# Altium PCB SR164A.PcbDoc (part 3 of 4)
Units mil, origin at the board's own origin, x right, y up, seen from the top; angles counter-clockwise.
Board outline 6100 x 4100 mil, 6 copper layers (Top Layer, Signal Layer 1, Signal Layer 2, Signal Layer 3, Signal Layer 4, Bottom Layer), stack 61.4 mil thick; 254 components, 116 nets, 656 pads, 2538 vias.
Unrouted connection lines stored in the file: 13.
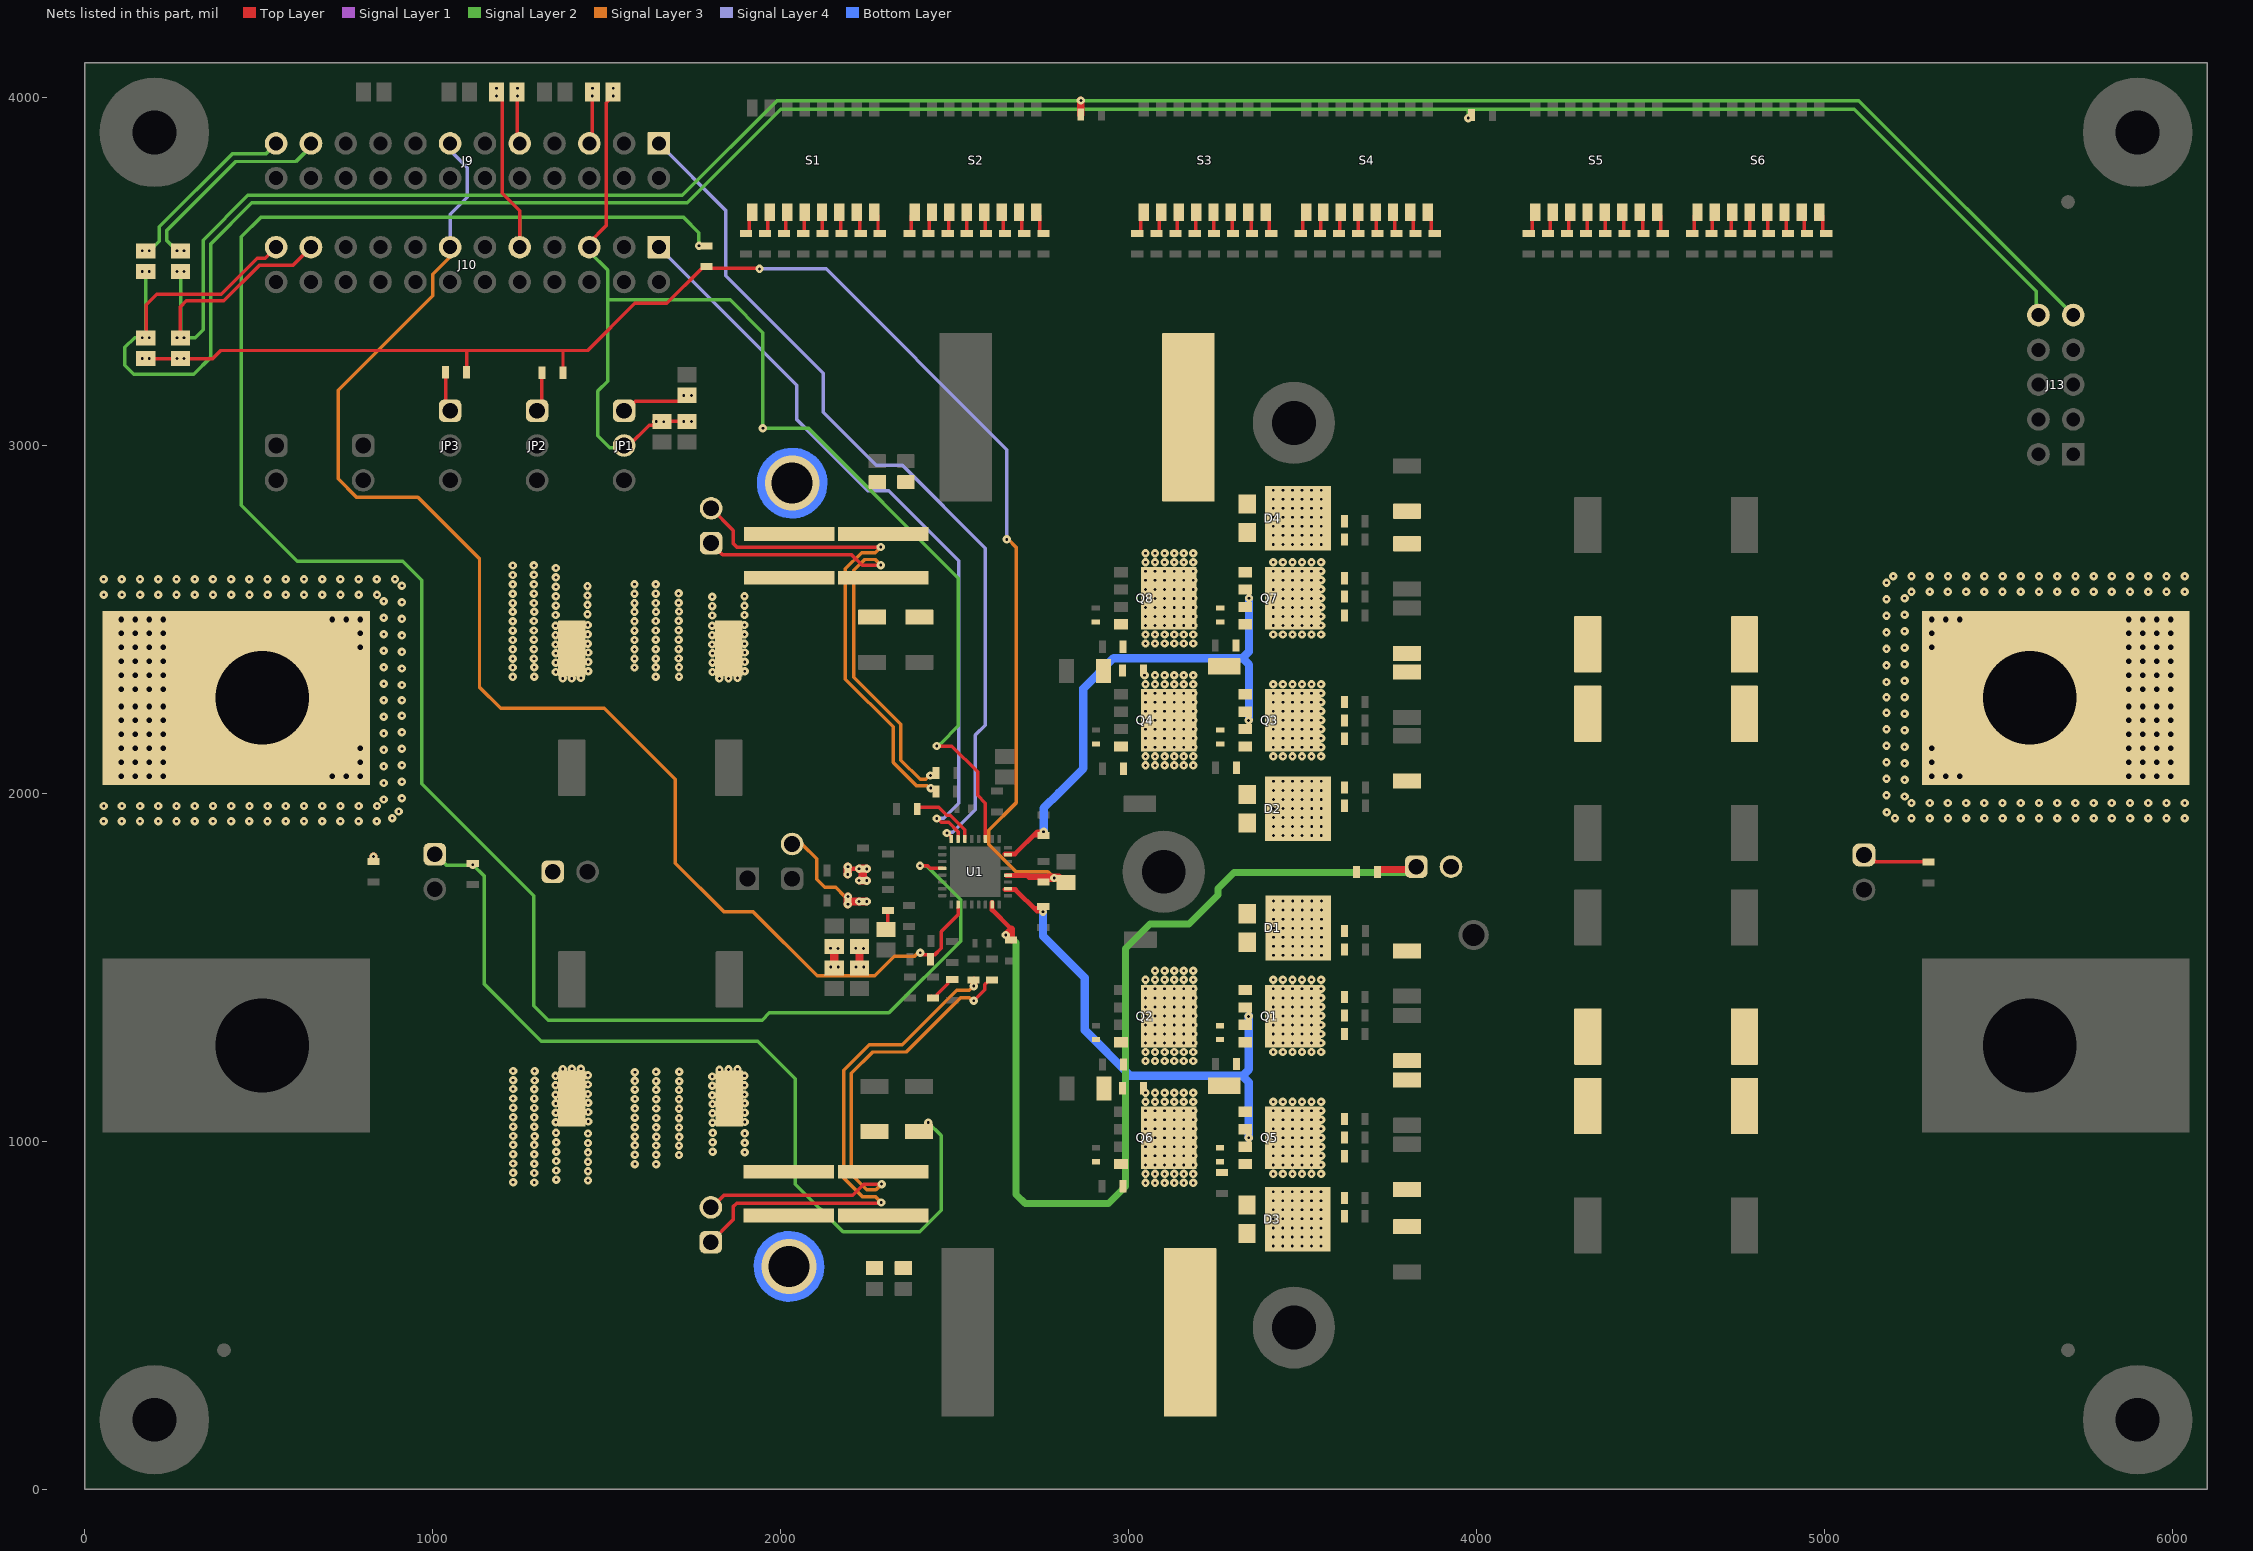
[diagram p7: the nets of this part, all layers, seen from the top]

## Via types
v1: diameter 24, hole 8, Top Layer to Bottom Layer, tented both sides, 2290 vias
v2: diameter 32, hole 16, Top Layer to Bottom Layer, 232 vias
v3: diameter 19.68, hole 7.87, Top Layer to Bottom Layer, tented both sides, 12 vias
v4: diameter 157.48, hole 118.11, Top Layer to Bottom Layer, tented both sides, 4 vias

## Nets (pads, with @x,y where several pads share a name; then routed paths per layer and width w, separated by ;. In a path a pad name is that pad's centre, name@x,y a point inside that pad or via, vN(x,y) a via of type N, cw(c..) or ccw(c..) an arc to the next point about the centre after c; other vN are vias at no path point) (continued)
NetC5_2: C5.2 R5.2 | length 87.8
  Top Layer w10: C5.2@2432.47,1417.54 C5.2@2437.93,1412.08 ; C5.2@2442.09,1414.7 2448.05,1414.7 2450.43,1417.08 2450.43,1423.04 2480.61,1453.22 2480.61,1460.72 2485.61,1465.72 R5.2@2493.11,1465.72
NetC9_2: C9.2 R29.2
NetC10_2: C10.2 R30.2
NetC16_1: C16.1 R8.1 | length 56.8
  Top Layer w10: C16.1@2302.35,1609.46 2308.21,1615.31 R8.1@2308.21,1663.87
NetC18_1: C18.1 JP5.2 R103.1 | length 364.2
  Top Layer w10: C18.1@2193.28,1692.52 2196.14,1689.66 v1(2225.5,1689.66) R103.1@2236.4,1689.66
  Top Layer w24: C18.1@2192.89,1689.7 R103.1@2247.29,1689.66 ; v1(2193.28,1681.63) C18.1@2193.28,1703.42
  Signal Layer 3 w10: JP5.2@2046.06,1854.79 2060.75,1854.79 2103.2,1812.34 2103.2,1753.81 2126.22,1730.79 2157.91,1730.79 2183.59,1705.11 v1@2193.45,1705.11
  other v1: 2247.46,1689.5 2193.45,1703.59
NetC19_1: C19.1 R103.2 R104.1 | length 178.5
  Top Layer w10: C19.1@2193.09,1778.19 C19.1@2199.65,1784.75 ; R104.1@2225.46,1779.28 2235.24,1779.28 2236.31,1780.34 2236.31,1749.75 R103.2@2236.4,1749.66
  Top Layer w12: C19.1@2197.32,1783.43 v1(2225.46,1783.43)
  Top Layer w24: v1(2193.09,1767.29) C19.1@2193.09,1789.08 ; v1(2225.46,1783.43) R104.1@2247.25,1783.43 ; v1(2225.5,1749.66) R103.2@2247.29,1749.66 ; R103.2@2236.31,1749.75 R104.1@2236.35,1783.43
  other v1: 2247.46,1749.5 2247.42,1783.26 2193.25,1789.25
NetJP1_1: JP1.1 R9.2 | length 202.3
  Top Layer w10: JP1.1@1550,3100 1555.52,3100 1583.34,3127.82 R9.2@1719.03,3127.82
  Top Layer w24: v1(1721.71,3143.92) R9.2@1743.51,3143.92
  other v1: 1743.67,3143.76
NetJP2_1: JP2.1 R89.1 | length 115
  Top Layer w10: JP2.1@1300,3100 1312.82,3112.82 1312.82,3207.44 R89.1@1314.41,3209.02
NetJP3_1: JP3.1 R90.1 | length 116.1
  Top Layer w10: R90.1@1037.3,3210.84 1038.03,3210.11 1038.03,3111.97 JP3.1@1050,3100
NetQ1_4: Q1.4 R21.1 R31.2
NetQ2_4: Q2.4 R22.2 R32.2
NetQ3_4: Q3.4 R23.2 R33.2
NetQ4_4: Q4.4 R24.1 R34.2
NetQ5_4: Q5.4 R25.1 R35.2
NetQ6_4: Q6.4 R26.2 R36.2
NetQ7_4: Q7.4 R27.2 R37.2
NetQ8_4: Q8.4 R28.1 R38.2
NetR41_1: R41.1 S1.1 | length 71.3
  Top Layer w10: R41.1@1900,3610 1905.09,3610 1910.09,3615 1910.09,3660.09 S1.1@1920,3670
NetR42_2: R42.2 S1.2 | length 67.7
  Top Layer w10: R42.2@1955,3610 1957.5,3610 1962.5,3615 1962.5,3662.5 S1.2@1970,3670
NetR43_1: R43.1 S1.3 | length 64.1
  Top Layer w10: R43.1@2010,3610 2015,3615 2015,3665 S1.3@2020,3670
NetR44_2: R44.2 S1.4 | length 62.1
  Top Layer w10: R44.2@2065,3610 2067.62,3612.62 2067.62,3667.62 S1.4@2070,3670
NetR45_1: R45.1 S1.5 | length 60
  Top Layer w10: R45.1@2120,3610 S1.5@2120,3670
NetR46_2: R46.2 S1.6 | length 62.1
  Top Layer w10: S1.6@2170,3670 2172.51,3667.49 2172.51,3612.49 R46.2@2175,3610
NetR47_2: R47.2 S1.7 | length 64.1
  Top Layer w10: S1.7@2220,3670 2227.52,3662.48 2227.52,3615 2230,3612.52 R47.2@2230,3610
NetR48_2: R48.2 S1.8 | length 66.3
  Top Layer w10: S1.8@2270,3670 2279.77,3660.23 2279.77,3615 2284.77,3610 R48.2@2285,3610
NetR49_2: R49.2 S2.1 | length 66.3
  Top Layer w10: R49.2@2370,3610 2370.23,3610 2375.23,3615 2375.23,3660.23 S2.1@2385,3670
NetR50_2: R50.2 S2.2 | length 64.1
  Top Layer w10: R50.2@2425,3610 2425,3612.52 2427.48,3615 2427.48,3662.48 S2.2@2435,3670
NetR51_2: R51.2 S2.3 | length 62.1
  Top Layer w10: R51.2@2480,3610 2482.49,3612.49 2482.49,3667.49 S2.3@2485,3670
NetR52_1: R52.1 S2.4 | length 60
  Top Layer w10: R52.1@2535,3610 S2.4@2535,3670
NetR53_2: R53.2 S2.5 | length 62.1
  Top Layer w10: S2.5@2585,3670 2587.38,3667.62 2587.38,3612.62 R53.2@2590,3610
NetR54_2: R54.2 S2.6 | length 64.1
  Top Layer w10: S2.6@2635,3670 2640,3665 2640,3615 R54.2@2645,3610
NetR55_2: R55.2 S2.7 | length 67.7
  Top Layer w10: S2.7@2685,3670 2692.5,3662.5 2692.5,3615 2697.5,3610 R55.2@2700,3610
NetR56_1: R56.1 S2.8 | length 71.3
  Top Layer w10: S2.8@2735,3670 2744.91,3660.09 2744.91,3615 2749.91,3610 R56.1@2755,3610
NetR57_1: R57.1 S3.1 | length 71.3
  Top Layer w10: R57.1@3025,3610 3030.09,3610 3035.09,3615 3035.09,3660.09 S3.1@3045,3670
NetR58_2: R58.2 S3.2 | length 67.7
  Top Layer w10: R58.2@3080,3610 3082.5,3610 3087.5,3615 3087.5,3662.5 S3.2@3095,3670
NetR59_1: R59.1 S3.3 | length 64.1
  Top Layer w10: R59.1@3135,3610 3140,3615 3140,3665 S3.3@3145,3670
NetR60_2: R60.2 S3.4 | length 62.1
  Top Layer w10: R60.2@3190,3610 3192.62,3612.62 3192.62,3667.62 S3.4@3195,3670
NetR61_1: R61.1 S3.5 | length 60
  Top Layer w10: R61.1@3245,3610 S3.5@3245,3670
NetR62_2: R62.2 S3.6 | length 62.1
  Top Layer w10: S3.6@3295,3670 3297.51,3667.49 3297.51,3612.49 R62.2@3300,3610
NetR63_2: R63.2 S3.7 | length 64.1
  Top Layer w10: S3.7@3345,3670 3352.52,3662.48 3352.52,3615 3355,3612.52 R63.2@3355,3610
NetR64_2: R64.2 S3.8 | length 66.3
  Top Layer w10: S3.8@3395,3670 3404.77,3660.23 3404.77,3615 3409.77,3610 R64.2@3410,3610
NetR65_2: R65.2 S4.1 | length 66.3
  Top Layer w10: R65.2@3495,3610 3495.23,3610 3500.23,3615 3500.23,3660.23 S4.1@3510,3670
NetR66_2: R66.2 S4.2 | length 64.1
  Top Layer w10: R66.2@3550,3610 3550,3612.52 3552.48,3615 3552.48,3662.48 S4.2@3560,3670
NetR67_2: R67.2 S4.3 | length 62.1
  Top Layer w10: R67.2@3605,3610 3607.49,3612.49 3607.49,3667.49 S4.3@3610,3670
NetR68_1: R68.1 S4.4 | length 60
  Top Layer w10: R68.1@3660,3610 S4.4@3660,3670
NetR69_2: R69.2 S4.5 | length 62.1
  Top Layer w10: S4.5@3710,3670 3712.38,3667.62 3712.38,3612.62 R69.2@3715,3610
NetR70_2: R70.2 S4.6 | length 64.1
  Top Layer w10: S4.6@3760,3670 3765,3665 3765,3615 R70.2@3770,3610
NetR71_2: R71.2 S4.7 | length 67.7
  Top Layer w10: S4.7@3810,3670 3817.5,3662.5 3817.5,3615 3822.5,3610 R71.2@3825,3610
NetR72_1: R72.1 S4.8 | length 71.3
  Top Layer w10: S4.8@3860,3670 3869.91,3660.09 3869.91,3615 3874.91,3610 R72.1@3880,3610
NetR73_1: R73.1 S5.1 | length 71.3
  Top Layer w10: R73.1@4150,3610 4155.09,3610 4160.09,3615 4160.09,3660.09 S5.1@4170,3670
NetR74_2: R74.2 S5.2 | length 67.7
  Top Layer w10: R74.2@4205,3610 4207.5,3610 4212.5,3615 4212.5,3662.5 S5.2@4220,3670
NetR75_1: R75.1 S5.3 | length 64.1
  Top Layer w10: R75.1@4260,3610 4265,3615 4265,3665 S5.3@4270,3670
NetR76_2: R76.2 S5.4 | length 62.1
  Top Layer w10: R76.2@4315,3610 4317.62,3612.62 4317.62,3667.62 S5.4@4320,3670
NetR77_1: R77.1 S5.5 | length 60
  Top Layer w10: R77.1@4370,3610 S5.5@4370,3670
NetR78_2: R78.2 S5.6 | length 62.1
  Top Layer w10: S5.6@4420,3670 4422.51,3667.49 4422.51,3612.49 R78.2@4425,3610
NetR79_2: R79.2 S5.7 | length 64.1
  Top Layer w10: S5.7@4470,3670 4477.52,3662.48 4477.52,3615 4480,3612.52 R79.2@4480,3610
NetR80_2: R80.2 S5.8 | length 66.3
  Top Layer w10: S5.8@4520,3670 4529.77,3660.23 4529.77,3615 4534.77,3610 R80.2@4535,3610
NetR81_2: R81.2 S6.1 | length 66.3
  Top Layer w10: R81.2@4620,3610.79 4620.23,3610.79 4625.23,3615.79 4625.23,3661.02 S6.1@4635,3670.79
NetR82_2: R82.2 S6.2 | length 64.1
  Top Layer w10: R82.2@4675,3610.79 4675,3613.31 4677.48,3615.79 4677.48,3663.27 S6.2@4685,3670.79
NetR83_2: R83.2 S6.3 | length 62.1
  Top Layer w10: R83.2@4730,3610.79 4732.49,3613.28 4732.49,3668.28 S6.3@4735,3670.79
NetR84_1: R84.1 S6.4 | length 60
  Top Layer w10: R84.1@4785,3610.79 S6.4@4785,3670.79
NetR85_2: R85.2 S6.5 | length 62.1
  Top Layer w10: S6.5@4835,3670.79 4837.38,3668.41 4837.38,3613.41 R85.2@4840,3610.79
NetR86_2: R86.2 S6.6 | length 64.1
  Top Layer w10: S6.6@4885,3670.79 4890,3665.79 4890,3615.79 R86.2@4895,3610.79
NetR87_2: R87.2 S6.7 | length 67.7
  Top Layer w10: S6.7@4935,3670.79 4942.5,3663.29 4942.5,3615.79 4947.5,3610.79 R87.2@4950,3610.79
NetR88_1: R88.1 S6.8 | length 71.3
  Top Layer w10: S6.8@4985,3670.79 4994.91,3660.88 4994.91,3615.79 4999.91,3610.79 R88.1@5005,3610.79
NetR91_2: R91.2 R93.1 | length 79.6
  Top Layer w24: v1(2215.85,1554.91) R93.1@2237.65,1554.91 ; v1(2216.62,1501.31) R91.2@2238.41,1501.31 ; R91.2@2226.78,1516.56 R93.1@2226.78,1552.6
  other v1: 2238.58,1501.15 2237.81,1554.74
NetR92_2: R92.2 R94.1 | length 79.6
  Top Layer w24: v1(2142.97,1554.91) R94.1@2164.76,1554.91 ; v1(2143.74,1501.31) R92.2@2165.53,1501.31 ; R92.2@2154.41,1515.86 R94.1@2154.41,1551.9
  other v1: 2165.7,1501.15 2164.93,1554.74
PGOOD: J10.9 R19.2 R98.1 U1.28 | length 6443.5
  Top Layer w10: v1(1183.28,4004.73) R98.1@1183.45,4004.9 ; R98.1@1183.54,4013.9 R98.1@1183.54,4015.75 ; R98.1@1187.99,4009.44 1199.69,3997.75 1199.69,3952.14 1199.69,3725.08 1250,3674.77 J10.9@1250,3570 ; v1(1765.12,3574.08) 1765.21,3574 1786.87,3574 R19.2@1786.95,3573.92 ; v1@2401.68,1792.54 2422.1,1792.54 2429.79,1784.84 U1.28@2464.51,1784.84
  Top Layer w24: R98.1@1183.45,4004.9 v1(1183.45,4026.69)
  Signal Layer 2 w10: J10.9@1250,3570 1250,3655.9 ; v1(1765.12,3574.08) 1765.12,3611.57 1720.79,3655.9 1308.61,3655.9 506.29,3655.9 449.9,3599.51 449.9,2828.38 610.96,2667.32 913.97,2667.32 968.87,2612.42 968.87,2027.91 1290.82,1705.96 1290.82,1389.65 1332.04,1348.43 1946.52,1348.43 1967.34,1369.25 2311.36,1369.25 2517.26,1575.15 2517.26,1592.6 2517.26,1694.42 2419.21,1792.47 v1(2400.54,1792.47)
  Signal Layer 3 w10: J10.9@1250,3555.3 J10.9@1250,3570
  Bottom Layer w24: v1@1183.45,4004.9 v1(1183.45,4026.69)
PGOOD_SEC: J9.9 R98.2 | length 182.8
  Top Layer w10: v1(1243.28,4004.73) 1243.28,3875.03 J9.9@1250,3868.31
  Top Layer w24: R98.2@1243.45,4004.9 v1(1243.45,4026.69)
  Bottom Layer w24: v1@1243.45,4004.9 v1(1243.45,4026.69)
RS1: J11.1 R1.1 R3.1 R11.2 R12.2 R16.2 | length 2089.8
  Top Layer w10: J11.1@1799.29,710.42 1863.12,774.25 1863.12,811.64 1873.22,821.74 v1@2286.79,821.74 ; R16.2@2554.63,1464.14 R16.2@2555.16,1463.61
  Top Layer w20: v1(2555.16,1446.33) R16.2@2555.16,1463.61
  Signal Layer 3 w10: v1(2288.9,824.49) 2273.1,840.29 2236.23,840.29 2181.63,894.89 2181.63,1204.43 2254.48,1277.28 2349.1,1277.28 2506.47,1434.65 2542.3,1434.65 2553.98,1446.33 v1(2555.16,1446.33)
  Bottom Layer w10: v4(2024,640.62) 2091.82,640.62 2104.57,627.87
  Bottom Layer w40: 2104.57,627.87 cw(c2024,640.62) 2104.84,629.72
RS2: J12.2 R2.2 R4.2 R13.1 R14.1 R18.2 | length 2101.6
  Top Layer w10: J12.2@1800,2819.54 1863.83,2755.71 1863.83,2718.32 1873.93,2708.22 v1@2287.5,2708.22 ; v1(2431.39,2015.34) 2440.92,2015.34 2445.92,2010.34 R18.2@2445.92,2005.78
  Signal Layer 3 w10: v1(2287.5,2708.14) 2271.36,2692 2232.68,2692 2186.11,2645.43 2186.11,2328.49 2323.33,2191.27 2323.33,2089.01 2389.56,2022.78 2420.16,2022.78 2426.91,2016.03 v1@2431.39,2016.03
  Bottom Layer w10: v4@1983,2892 v4(2033,2892) 2043.9,2881.1 2113.85,2881.1
  Bottom Layer w40: 2113.57,2879.25 cw(c2033,2892) 2113.85,2881.1
RT: R6.2 U1.22 | length 181.3
  Top Layer w10: R6.2@2400.95,1960.35 2454.57,1960.35 2477.41,1937.52 2487.35,1937.52 2529.47,1895.39 U1.22@2529.47,1869.49
SCL: J10.21 J13.9 R39.1 R102.1 R106.1 | length 7111.9
  Top Layer w10: v1(265,3310) v1(285,3310) ; R102.1@275,3310.86 275,3399.14 291.57,3415.71 399.65,3415.71 502.75,3518.81 598.81,3518.81 J10.21@650,3570
  Top Layer w22: R39.1@2862.44,3951.1 v1@2862.44,3991.42
  Signal Layer 1 w24: v1(265,3310) v1(285,3310) ; v1(265,3500) v1(285,3500)
  Signal Layer 2 w10: v1@275.52,3310 275.52,3499.48 276.05,3500 v1(285,3500) ; v1(285,3310) 317.5,3310 340.29,3332.79 340.29,3590.25 468.88,3718.84 1716.78,3718.84 1989.36,3991.42 v1(2862.94,3991.42) 5098.58,3991.42 J13.9@5715,3375
  Signal Layer 2 w24: v1(265,3310) 275.52,3310 v1(285,3310) ; v1(265,3500) 275.52,3500 v1(285,3500)
  Signal Layer 3 w24: v1(265,3310) v1(285,3310) ; v1(265,3500) v1(285,3500)
  Signal Layer 4 w24: v1(265,3310) v1(285,3310) ; v1(265,3500) v1(285,3500)
  Bottom Layer w24: v1(265,3310) v1(285,3310) ; v1(265,3500) v1(285,3500)
SCL_SEC: J9.21 R106.2 | length 693.2
  Signal Layer 1 w24: v1(265,3560) v1(285,3560)
  Signal Layer 2 w10: v1(265,3560) 235.89,3589.11 235.89,3618.13 434.06,3816.3 606.92,3816.3 650,3859.38 J9.21@650,3868.31
  Signal Layer 2 w24: v1(265,3560) v1(285,3560)
  Signal Layer 3 w24: v1(265,3560) v1(285,3560)
  Signal Layer 4 w24: v1(265,3560) v1(285,3560)
  Bottom Layer w24: v1(265,3560) v1(285,3560)
SDA: J10.23 J13.10 R40.1 R101.1 R105.1 | length 7401
  Top Layer w10: R101.1@176.53,3311.05 176.53,3405 206.57,3435.04 391.92,3435.04 495.36,3538.48 518.48,3538.48 J10.23@550,3570
  Top Layer w22: v1(3975.98,3941.04) R40.1@3983.2,3948.28
  Signal Layer 1 w24: v1(165,3310) v1(185,3310) ; v1(165,3500) v1(185,3500)
  Signal Layer 2 w10: v1(165,3310) 143.08,3310 115.03,3281.95 115.03,3230.35 140.86,3204.51 312.6,3204.51 362.61,3254.52 362.61,3580.35 479.62,3697.36 1731.13,3697.36 2000.47,3966.7 2852.48,3966.7 2852.63,3966.55 3975.98,3966.55 ; v1(165,3500) 175.4,3500 v1(185,3500) ; v1@174.92,3500 174.92,3310 v1(185,3310) ; v1(3975.98,3941.04) 3975.98,3966.55 ; J13.10@5609.09,3375.35 5609.09,3443.5 5086.04,3966.55 3975.98,3966.55
  Signal Layer 2 w24: v1(165,3310) 174.92,3310 v1(185,3310) ; v1(165,3500) 174.92,3500 v1(185,3500)
  Signal Layer 3 w24: v1(165,3310) v1(185,3310) ; v1(165,3500) v1(185,3500)
  Signal Layer 4 w24: v1(165,3310) v1(185,3310) ; v1(165,3500) v1(185,3500)
  Bottom Layer w24: v1(165,3310) v1(185,3310) ; v1(165,3500) v1(185,3500)
SDA_SEC: J9.23 R105.2 | length 614.7
  Signal Layer 1 w24: v1(165,3560) v1(185,3560)
  Signal Layer 2 w10: v1@186.76,3560.33 213.9,3587.47 213.9,3628.24 423.56,3837.9 519.59,3837.9 J9.23@550,3868.31
  Signal Layer 2 w24: v1(165,3560) v1(185,3560)
  Signal Layer 3 w24: v1(165,3560) v1(185,3560)
  Signal Layer 4 w24: v1(165,3560) v1(185,3560)
  Bottom Layer w24: v1(165,3560) v1(185,3560)
SS: C8.1 J9.13 J10.13 U1.2 | length 3997.4
  Top Layer w10: v1(2401.07,1542.1) 2404.86,1542.1 2411.12,1535.84 2426.16,1535.84 2431.16,1530.84 C8.1@2431.16,1523.34 ; C8.1@2436.16,1535.84 2442.17,1535.84 2461.41,1555.08 2461.41,1603.2 2509.79,1651.59 U1.2@2509.79,1673.7
  Signal Layer 3 w10: J10.13@1063.59,3555.76 999.85,3492.02 999.85,3430.33 728.49,3158.97 728.49,2904.1 780.85,2851.74 957.6,2851.74 1134.44,2674.9 1134.44,2305.16 1195,2244.6 1492.69,2244.6 1696.92,2040.37 1696.92,1799.95 1836.22,1660.64 1920.31,1660.64 2105.2,1475.74 2270.1,1475.74 2325.95,1531.6 2384.72,1531.6 v1@2402.44,1549.31
  Signal Layer 4 w10: J10.13@1050,3570 1050,3664.15 1099.5,3713.65 1099.5,3798.87 1060.52,3837.85 1060.52,3857.79 J9.13@1050,3868.31
SW1: C9.1 C13.1 D1.1 D1.2 D3.1 D3.2 L1.1 Q1.1 Q1.2 Q1.3 Q2.5 Q5.1 Q5.2 Q5.3 Q6.5 R31.1 R35.1 TP1.1 U1.10 | length 1428.8
  Top Layer w10: 2725.72,1672.26 C13.1@2755.72,1672.26
  Top Layer w13.5: U1.10@2644.7,1723.79 2674.71,1723.79 2736.9,1661.6 2752.72,1661.6 v1(2754.12,1660.21)
  Bottom Layer w24: v1(2754.12,1660.21) 2754.12,1589.91 2874.04,1469.99 2874.04,1319.43 3005.12,1188.35 3327.01,1188.35 ; v1(3345.56,1010.69) 3345.56,1169.79 3327.01,1188.35 ; v1@3345.56,1360.69 3345.56,1206.9 3327.01,1188.35
  other v1: 3048.51,880.71 3076.01,880.71 3103.51,880.71 3131.01,880.71 3158.51,880.71 3186.01,880.71 3048.51,906.63 3076.01,906.63 3103.51,906.63 3131.01,906.63 3158.51,906.63 3186.01,906.63 3048.51,932.56 3076.01,932.56 3103.51,932.56 3131.01,932.56 3158.51,932.56 3186.01,932.56 3048.51,958.49 3076.01,958.49 3103.51,958.49 3131.01,958.49 3158.51,958.49 3186.01,958.49 3048.51,984.41 3076.01,984.41 3103.51,984.41 3131.01,984.41 3158.51,984.41 3186.01,984.41 3048.51,1010.34 3076.01,1010.34 3103.51,1010.34 3131.01,1010.34 3158.51,1010.34 3186.01,1010.34 3048.51,1036.26 3076.01,1036.26 3103.51,1036.26 3131.01,1036.26 3158.51,1036.26 3186.01,1036.26 3048.51,1062.19 3076.01,1062.19 3103.51,1062.19 3131.01,1062.19 3158.51,1062.19 3186.01,1062.19 3048.51,1088.12 3076.01,1088.12 3103.51,1088.12 3131.01,1088.12 3158.51,1088.12 3186.01,1088.12 3048.51,1114.04 3076.01,1114.04 3103.51,1114.04 3131.01,1114.04 3158.51,1114.04 3186.01,1114.04 3048.51,1139.97 3076.01,1139.97 3103.51,1139.97 3131.01,1139.97 3158.51,1139.97 3186.01,1139.97 3048.55,1231.03 3076.05,1231.03 3103.55,1231.03 3131.05,1231.03 3158.55,1231.03 3186.05,1231.03 3048.55,1256.96 3076.05,1256.96 3103.55,1256.96 3131.05,1256.96 3158.55,1256.96 3186.05,1256.96 3048.55,1282.88 3076.05,1282.88 3103.55,1282.88 3131.05,1282.88 3158.55,1282.88 3186.05,1282.88 3048.55,1308.81 3076.05,1308.81 3103.55,1308.81 3131.05,1308.81 3158.55,1308.81 3186.05,1308.81 3048.55,1334.73 3076.05,1334.73 3103.55,1334.73 3131.05,1334.73 3158.55,1334.73 3186.05,1334.73 3345,1359.23 3048.55,1360.66 3076.05,1360.66 3103.55,1360.66 3131.05,1360.66 3158.55,1360.66 3186.05,1360.66 3048.55,1386.59 3076.05,1386.59 3103.55,1386.59 3131.05,1386.59 3158.55,1386.59 3186.05,1386.59 3048.55,1412.51 3076.05,1412.51 3103.55,1412.51 3131.05,1412.51 3158.55,1412.51 3186.05,1412.51 3048.55,1438.44 3076.05,1438.44 3103.55,1438.44 3131.05,1438.44 3158.55,1438.44 3186.05,1438.44 3048.55,1464.37 3076.05,1464.37 3103.55,1464.37 3131.05,1464.37 3158.55,1464.37 3186.05,1464.37 3076.05,1490.29 3103.55,1490.29 3131.05,1490.29 3158.55,1490.29 3186.05,1490.29
SW2: C10.1 C14.2 D2.1 D2.2 D4.1 D4.2 L2.2 Q3.1 Q3.2 Q3.3 Q4.5 Q7.1 Q7.2 Q7.3 Q8.5 R33.1 R37.1 TP2.1 U1.15 | length 1489
  Top Layer w10: 2728.05,1878.91 C14.2@2758.05,1878.91 ; v1(2755.75,1890.26) v1@2759.54,1890.26
  Top Layer w13.5: U1.15@2644.7,1826.21 2673.52,1826.21 2737.36,1890.04 2755.53,1890.04 v1(2755.75,1890.26)
  Bottom Layer w24: v1(2755.75,1890.26) 2755.75,1957.76 2799.59,2001.6 2870,2072.01 2870,2301.79 2957.06,2388.85 3327.3,2388.85 ; v1@3345.86,2211.2 3345.86,2370.3 3327.3,2388.85 ; v1(3345.86,2561.2) 3345.86,2407.41 3327.3,2388.85
  other v1: 3048.51,2080.7 3076.01,2080.7 3103.51,2080.7 3131.01,2080.7 3158.51,2080.7 3186.01,2080.7 3048.51,2106.63 3076.01,2106.63 3103.51,2106.63 3131.01,2106.63 3158.51,2106.63 3186.01,2106.63 3048.51,2132.56 3076.01,2132.56 3103.51,2132.56 3131.01,2132.56 3158.51,2132.56 3186.01,2132.56 3048.51,2158.48 3076.01,2158.48 3103.51,2158.48 3131.01,2158.48 3158.51,2158.48 3186.01,2158.48 3048.51,2184.41 3076.01,2184.41 3103.51,2184.41 3131.01,2184.41 3158.51,2184.41 3186.01,2184.41 3048.51,2210.34 3076.01,2210.34 3103.51,2210.34 3131.01,2210.34 3158.51,2210.34 3186.01,2210.34 3345,2210 3048.51,2236.26 3076.01,2236.26 3103.51,2236.26 3131.01,2236.26 3158.51,2236.26 3186.01,2236.26 3048.51,2262.19 3076.01,2262.19 3103.51,2262.19 3131.01,2262.19 3158.51,2262.19 3186.01,2262.19 3048.51,2288.11 3076.01,2288.11 3103.51,2288.11 3131.01,2288.11 3158.51,2288.11 3186.01,2288.11 3048.51,2314.04 3076.01,2314.04 3103.51,2314.04 3131.01,2314.04 3158.51,2314.04 3186.01,2314.04 3046.05,2339.96 3076.01,2339.97 3103.51,2339.97 3131.01,2339.97 3158.51,2339.97 3186.01,2339.97 3048.55,2431.03 3076.05,2431.03 3103.55,2431.03 3131.05,2431.03 3158.55,2431.03 3186.05,2431.03 3048.55,2456.96 3076.05,2456.96 3103.55,2456.96 3131.05,2456.96 3158.55,2456.96 3186.05,2456.96 3048.55,2482.88 3076.05,2482.88 3103.55,2482.88 3131.05,2482.88 3158.55,2482.88 3186.05,2482.88 3048.55,2508.81 3076.05,2508.81 3103.55,2508.81 3131.05,2508.81 3158.55,2508.81 3186.05,2508.81 3048.55,2534.73 3076.05,2534.73 3103.55,2534.73 3131.05,2534.73 3158.55,2534.73 3186.05,2534.73 3048.55,2560.66 3076.05,2560.66 3103.55,2560.66 3131.05,2560.66 3158.55,2560.66 3186.05,2560.66 3048.55,2586.59 3076.05,2586.59 3103.55,2586.59 3131.05,2586.59 3158.55,2586.59 3186.05,2586.59 3048.55,2612.51 3076.05,2612.51 3103.55,2612.51 3131.05,2612.51 3158.55,2612.51 3186.05,2612.51 3048.55,2638.44 3076.05,2638.44 3103.55,2638.44 3131.05,2638.44 3158.55,2638.44 3186.05,2638.44 3048.55,2664.37 3076.05,2664.37 3103.55,2664.37 3131.05,2664.37 3158.55,2664.37 3186.05,2664.37 3048.55,2690.29 3076.05,2690.29 3103.55,2690.29 3131.05,2690.29 3158.55,2690.29 3186.05,2690.29
SYNCIN: J9.1 U1.24 | length 2492.7
  Top Layer w10: v1(2477.8,1886.36) 2481.76,1882.4 2483.92,1882.4 2490.1,1876.22 U1.24@2490.1,1869.49
  Signal Layer 4 w10: J9.1@1650,3868.31 1842.71,3675.6 1842.71,3487.54 2122.17,3208.07 2122.17,3095.22 2274.36,2943.02 2350.09,2943.02 2588.29,2704.83 2588.29,2196.44 2559.74,2167.89 2559.74,2001.6 2559.74,1953.37 2494.36,1887.98 2479.42,1887.98 v1(2477.8,1886.36)
SYNCOUT: J10.1 U1.23 | length 2169.6
  Top Layer w10: v1(2448.55,1928.21) 2450.19,1928.21 2461.41,1917 2482.56,1917 2509.71,1889.85 2509.71,1869.57 U1.23@2509.79,1869.49
  Signal Layer 4 w10: J10.1@1650,3570 2046.34,3173.66 2046.34,3074.76 2250.92,2870.18 2311.14,2870.18 2512.26,2669.05 2512.26,2001.6 2512.26,1972.27 2468.21,1928.21 v1(2448.55,1928.21)
UVLO/EN: C20.1 J10.5 JP1.2 R10.1 R96.1 U1.19 | length 3760.6
  Top Layer w10: J10.5@1450,3570 1450,3583.11 1499.18,3632.29 1499.18,3985.27 v1(1518.64,4004.73) ; JP1.2@1550,3000 1563.11,3000 1621.83,3058.72 1635.97,3058.72 1642.48,3065.23 C20.1@1642.48,3068.72 ; C20.1@1646.53,3064.67 C20.1@1651.53,3069.67 ; C20.1@1653.53,3069.67 1664.22,3069.67 R10.1@1709.19,3069.67 ; R10.1@1715.19,3069.67 R10.1@1725.03,3069.67 ; v1(2448.5,2136.24) 2492.12,2136.24 2565.96,2062.4 2565.96,1994.38 2588.53,1971.81 U1.19@2588.53,1869.49
  Top Layer w24: R96.1@1518.81,4004.9 v1(1518.81,4026.69) ; v1(1642.26,3068.72) C20.1@1664.06,3068.72 ; v1(1721.71,3069.13) R10.1@1743.51,3069.13
  Signal Layer 2 w10: J10.5@1450,3556.89 1502.46,3504.43 1502.46,3418.6 ; JP1.2@1550,3000 1544.12,2994.12 1508.38,2994.12 1473.86,3028.64 1473.86,3156.68 1502.46,3185.28 1502.46,3418.6 ; v1(1948.82,3049.35) 1948.82,3324.59 1854.8,3418.6 1502.46,3418.6 ; v1@1948.82,3050.28 2079.72,3050.28 2510.91,2619.09 2510.91,2194.51 2459.65,2143.24 2459.29,2143.24 2451.77,2135.73 v1@2451.77,2135.37
  Bottom Layer w24: v1@1518.81,4004.9 v1(1518.81,4026.69)
  other v1: 1664.22,3068.55 1743.67,3068.96
UVLO/EN_SEC: J9.5 R96.2 | length 183.6
  Top Layer w10: J9.5@1450,3868.31 1458.64,3876.95 v1(1458.64,4004.73)
  Top Layer w24: R96.2@1458.81,4004.9 v1(1458.81,4026.69)
  Bottom Layer w24: v1@1458.81,4004.9 v1(1458.81,4026.69)
VCC: C3.1 C4.1 R19.1 R89.2 R90.2 R101.2 R102.2 U1.12 | length 4784.9
  Top Layer w10: R101.2@167.58,3250.98 R101.2@185,3250.98 ; v1(185,3250) v1(265,3250) ; R102.2@265,3250.98 R102.2@285,3250.98 ; v1(285,3250) 367.38,3250 390.51,3273.13 1097.3,3273.14 ; R90.2@1097.3,3210.84 1097.3,3273.14 ; R89.2@1374.41,3209.02 1374.41,3273.14 ; v1(1939.01,3507.65) 1937.77,3508.89 1805.31,3508.89 1791.95,3508.92 R19.1@1786.95,3513.92 1781.95,3508.92 1772.84,3508.92 1672.93,3409.01 1581.18,3409.01 1445.31,3273.14 1374.41,3273.14 ; C3.1@2762.05,1751.2 2762.82,1750.43 C4.1@2805,1750.43 ; C4.1@2805.11,1749.93 2814.53,1749.93 C4.1@2819.75,1744.71 ; 1097.3,3273.14 1374.41,3273.14
  Top Layer w13.5: U1.12@2648,1764.4 2700.25,1764.27 2714.1,1764.24
  Top Layer w18: 2714.1,1760.47 2800.25,1760.47 2801.08,1759.64 2801.08,1757.86 C4.1@2805,1753.94 ; C4.1@2805.11,1753.44 2813.84,1744.71 C4.1@2819.75,1744.71
  Signal Layer 1 w24: v1(165,3250) v1(185,3250) ; v1(265,3250) v1(285,3250)
  Signal Layer 2 w24: v1(165,3250) v1(185,3250) ; v1(265,3250) v1(285,3250)
  Signal Layer 3 w10: v1(2650.01,2730.3) 2653.8,2730.3 2677.75,2706.35 2677.75,1974.11 2597.9,1894.26 2597.9,1853.37 2676.36,1774.91 2768.29,1774.91 v1(2786.25,1756.95)
  Signal Layer 3 w24: v1(165,3250) v1(185,3250) ; v1(265,3250) v1(285,3250)
  Signal Layer 4 w10: v1(1939.01,3507.65) 2130.5,3507.65 2650.01,2988.14 v1(2650.01,2730.3)
  Signal Layer 4 w24: v1(165,3250) v1(185,3250) ; v1(265,3250) v1(285,3250)
  Bottom Layer w24: v1(165,3250) v1(185,3250) ; v1(265,3250) v1(285,3250)
VIN: C21.2 C22.2 C23.2 C24.2 C25.2 C26.2 C27.2 C28.2 C29.1 C30.1 J1.1 J5.1 J11.2 J12.1 JP4.1 R1.2 R2.1 R3.2 R4.1 R15.2 R17.2 T1.1 | length 5411.4
  Top Layer w10: J11.2@1800,808.56 1837.07,845.63 2168.37,845.63 2207.15,845.63 2238.68,877.16 v1(2290.1,877.16) ; v1(2287.86,2656.35) 2233.98,2656.35 2203.71,2686.61 1832.93,2686.61 ; v1(2430.4,2051.81) 2441.08,2051.81 2446.08,2056.81 R17.2@2446.08,2059.06 ; v1(2555.23,1404.44) 2586.81,1436.02 2586.81,1450.85 2595.1,1459.14 2600.1,1464.14 R15.2@2607.6,1464.14 ; 1832.93,2686.61 J12.1@1800,2719.54 1832.93,2686.61
  Top Layer w23: C29.1@829.44,1808.52 v1@829.44,1818.52
  Signal Layer 2 w10: J5.1@1007,1825 1008.64,1825 1039.32,1794.33 1114.07,1794.33 v1(1115.11,1795.37) 1148.73,1761.76 1148.73,1451.27 1311.72,1288.28 1934.47,1288.28 2042.26,1180.5 2042.26,877.27 2179.17,740.36 2399.39,740.36 2461.28,802.25 2461.28,1016.92 v1(2424.13,1054.07)
  Signal Layer 3 w10: 2210.36,2641.16 2241.62,2672.42 2271.79,2672.42 v1(2287.86,2656.35) ; 2210.36,2642.03 2210.36,2333.64 2345.57,2198.43 2345.57,2095.94 2400.85,2040.66 2417.54,2040.66 2428.7,2051.81 v1(2430.4,2051.81) ; v1(2290.1,877.16) 2273.86,860.92 2247.46,860.92 2203.17,905.21 2203.17,1195.45 2264.68,1256.96 2360.55,1256.96 2516.87,1413.27 2542.61,1413.27 2551.44,1404.44 v1(2555.23,1404.44)
  other v1: 1231.11,882.49 1291.92,882.02 1446.11,887.49 1355.15,889.49 1231.11,909.49 1291.92,909.02 1446.11,914.49 1355.15,916.49 1641.92,934.34 1581.11,934.81 1231.11,936.49 1291.92,936.02 1446.11,941.49 1355.15,943.49 1641.92,961.34 1707.74,960.87 1581.11,961.81 1231.11,963.49 1291.92,963.02 1446.11,968.49 1897,969.06 1355.15,970.49 1804.37,970.38 1641.92,988.34 1707.74,987.87 1581.11,988.81 1231.11,990.49 1291.92,990.02 1446.11,995.49 1897,996.06 1355.15,997.49 1804.37,997.38 1642.88,1013.34 1708.7,1012.87 1581.11,1013.81 1231.11,1015.49 1292.88,1015.02 1446.11,1022.49 1897,1023.06 1354.29,1024.59 1804.77,1024.5 1641.92,1040.34 1707.74,1039.87 1581.11,1040.81 1231.11,1042.49 1291.92,1042.02 1804.03,1053.63 1353.85,1055.32 1897.07,1055.67 1446.89,1057.36 1641.92,1067.34 1707.74,1066.87 1581.11,1067.81 1231.11,1069.49 1291.92,1069.02 1804.03,1080.63 1353.85,1082.32 1897.07,1082.67 1446.89,1084.36 1641.92,1094.34 1707.74,1093.87 1581.11,1094.81 1231.11,1096.49 1291.92,1096.02 1804.03,1107.63 1353.85,1109.32 1897.07,1109.67 1446.89,1111.36 1641.92,1121.34 1707.74,1120.87 1581.11,1121.81 1231.11,1123.49 1291.92,1123.02 1803.07,1132.63 1352.89,1134.32 1896.11,1134.67 1445.93,1136.36 1641.92,1148.34 1707.74,1147.87 1581.11,1148.81 1231.11,1150.49 1291.92,1150.02 1803.07,1159.63 1352.89,1161.32 1896.11,1161.67 1445.93,1163.36 1641.92,1173.34 1708.7,1172.87 1581.11,1173.81 1231.11,1175.49 1292.88,1175.02 1803.07,1186.63 1352.89,1188.32 1896.11,1188.67 1445.93,1190.36 1581.11,1198.81 1641.92,1200.34 1708.7,1199.87 1231.11,1202.49 1292.88,1202.02 1824.06,1206.12 1850.19,1207 1876.06,1207.08 1373.88,1207.8 1400.01,1208.69 1425.88,1208.77 829.68,1818.73 54.09,1919.88 106.44,1919.88 158.79,1919.88 211.14,1919.88 263.49,1919.88 315.84,1919.88 368.19,1919.88 420.54,1919.88 472.89,1919.88 525.24,1919.88 577.59,1919.88 629.94,1919.88 682.29,1919.88 734.64,1919.88 786.99,1919.88 839.34,1919.88 883.72,1928.45 902.44,1948.12 54.36,1964.04 106.71,1964.04 159.06,1964.04 211.41,1964.04 263.76,1964.04 316.11,1964.04 368.46,1964.04 420.81,1964.04 473.16,1964.04 525.51,1964.04 577.86,1964.04 630.21,1964.04 682.56,1964.04 734.91,1964.04 787.26,1964.04 839.61,1964.04 859.29,1982.76 911.37,1986.08 859.29,2030.24 911.37,2033.57 859.29,2077.73 911.37,2081.05 859.29,2125.21 911.37,2128.54 859.29,2172.7 911.37,2176.02 859.29,2220.18 911.37,2223.51 859.29,2267.67 911.37,2267.67 911.37,2311.83 859.29,2315.15 1373.76,2330.77 1399.85,2330.65 1823.94,2330.77 1850.03,2330.65 1425.76,2331.73 1875.94,2331.73 1230,2335 1291.78,2335.47 1640.82,2335.47 1707.59,2335.94 1353.71,2349.18 1803.89,2349.18 1446.75,2351.22 1896.93,2351.22 911.37,2359.32 1230,2362 1291.78,2362.47 1580,2362 1640.82,2362.47 859.29,2362.64 1707.59,2362.94 1353.71,2376.18 1803.89,2376.18 1446.75,2378.22 1896.93,2378.22 1230,2387 1290.82,2387.47 1580,2387 1640.82,2387.47 1706.63,2387.94 1353.71,2403.18 1803.89,2403.18 1446.75,2405.22 1896.93,2405.22 911.37,2406.8 859.29,2410.12 1230,2414 1290.82,2414.47 1580,2414 1640.82,2414.47 1706.63,2414.94 1352.75,2428.18 1802.93,2428.18 1445.79,2430.22 1895.97,2430.22 1230,2441 1290.82,2441.47 1580,2441 1640.82,2441.47 1706.63,2441.94 911.37,2454.28 1352.75,2455.18 1802.93,2455.18 1445.79,2457.22 1895.97,2457.22 859.29,2457.61 1230,2468 1290.82,2468.47 1580,2468 1640.82,2468.47 1706.63,2468.94 1352.75,2482.18 1802.93,2482.18 1445.79,2484.22 1895.97,2484.22 1230,2495 1290.82,2495.47 1580,2495 1640.82,2495.47 1706.63,2495.94 911.37,2501.77 859.29,2505.09 1803.67,2511.31 1353.18,2512.91 1895.9,2512.75 1445,2515 1230,2522 1291.78,2522.47 1580,2522 1641.78,2522.47 1707.59,2522.94 1803.27,2538.43 1354.04,2540 1895.9,2539.75 1445,2542 1230,2547 1290.82,2547.47 1580,2547 1640.82,2547.47 1706.63,2547.94 911.37,2549.25 859.29,2552.58 1803.27,2565.43 1354.04,2567 1895.9,2566.75 1445,2569 54.36,2571.3 106.71,2571.3 159.06,2571.3 211.41,2571.3 263.76,2571.3 316.11,2571.3 368.46,2571.3 420.81,2571.3 473.16,2571.3 525.51,2571.3 577.86,2571.3 630.21,2571.3 682.56,2571.3 734.91,2571.3 787.26,2571.3 839.61,2571.3 1230,2574 1290.82,2574.47 1580,2574 1640.82,2574.47 1706.63,2574.94 1354.04,2594 1445,2596 911.37,2596.74 1230,2601 1290.82,2601.47 1580,2601 1640.82,2601.47 54.09,2615.46 106.44,2615.46 158.79,2615.46 211.14,2615.46 263.49,2615.46 315.84,2615.46 368.19,2615.46 420.54,2615.46 472.89,2615.46 525.24,2615.46 577.59,2615.46 629.94,2615.46 682.29,2615.46 734.64,2615.46 786.99,2615.46 839.34,2615.46 891.69,2615.46 1354.04,2621 1230,2628 1290.82,2628.47 1354.04,2648 1230,2655 1290.82,2655.47
  other v2: 105,2050 145,2050 185,2050 225,2050 711.27,2050 751.27,2050 791.27,2050 105,2090 145,2090 185,2090 225,2090 791.27,2090 105,2130 145,2130 185,2130 225,2130 791.27,2130 105,2170 145,2170 185,2170 225,2170 105,2210 145,2210 185,2210 225,2210 105,2250 145,2250 185,2250 225,2250 105,2300 145,2300 185,2300 225,2300 105,2340 145,2340 185,2340 225,2340 105,2380 145,2380 185,2380 225,2380 105,2420 145,2420 185,2420 225,2420 791.27,2420 105,2460 145,2460 185,2460 225,2460 791.27,2460 105,2500 145,2500 185,2500 225,2500 711.27,2500 751.27,2500 791.27,2500
VOUT: C31.2 C32.2 C33.2 C34.2 C35.2 C36.2 C37.2 C38.2 C39.2 C40.2 C41.1 C42.1 C43.1 C44.1 C45.1 C46.1 C47.1 C48.1 C49.1 C50.1 C51.1 C52.1 C53.1 C54.1 C55.1 C56.1 C57.1 C58.1 C59.1 C60.1 C61.2 C62.2 C63.2 C64.2 C65.2 C66.2 C67.2 C68.2 C69.1 D1.3 D2.3 D3.3 D4.3 J3.1 J6.1 JP6.2 Q1.5 Q3.5 Q5.5 Q7.5 R20.1 T3.1 | length 212.4
  Top Layer w10: J6.1@5113.46,1822.62 5125.33,1822.62 5143.84,1804.1 5297.96,1804.1 C69.1@5299.21,1802.85 ; J6.1@5125.39,1806.49 J6.1@5143.84,1806.49
  other v1: 3415.61,699.61 3443.11,699.61 3470.61,699.61 3498.11,699.61 3525.61,699.61 3553.11,699.61 3415.61,725.54 3443.11,725.54 3470.61,725.54 3498.11,725.54 3525.61,725.54 3553.11,725.54 3415.61,751.47 3443.11,751.47 3470.61,751.47 3498.11,751.47 3525.61,751.47 3553.11,751.47 3415.61,777.39 3443.11,777.39 3470.61,777.39 3498.11,777.39 3525.61,777.39 3553.11,777.39 3415.61,803.32 3443.11,803.32 3470.61,803.32 3498.11,803.32 3525.61,803.32 3553.11,803.32 3415.61,829.25 3443.11,829.25 3470.61,829.25 3498.11,829.25 3525.61,829.25 3553.11,829.25 3415.61,855.17 3443.11,855.17 3470.61,855.17 3498.11,855.17 3525.61,855.17 3553.11,855.17 3415.85,906.63 3443.35,906.63 3470.85,906.63 3498.35,906.63 3525.85,906.63 3553.35,906.63 3415.85,932.56 3443.35,932.56 3470.85,932.56 3498.35,932.56 3525.85,932.56 3553.35,932.56 3415.85,958.49 3443.35,958.49 3470.85,958.49 3498.35,958.49 3525.85,958.49 3553.35,958.49 3415.85,984.41 3443.35,984.41 3470.85,984.41 3498.35,984.41 3525.85,984.41 3553.35,984.41 3415.85,1010.34 3443.35,1010.34 3470.85,1010.34 3498.35,1010.34 3525.85,1010.34 3553.35,1010.34 3415.85,1036.26 3443.35,1036.26 3470.85,1036.26 3498.35,1036.26 3525.85,1036.26 3553.35,1036.26 3415.85,1062.19 3443.35,1062.19 3470.85,1062.19 3498.35,1062.19 3525.85,1062.19 3553.35,1062.19 3415.85,1088.12 3443.35,1088.12 3470.85,1088.12 3498.35,1088.12 3525.85,1088.12 3553.35,1088.12 3415.85,1114.04 3443.35,1114.04 3470.85,1114.04 3498.35,1114.04 3525.85,1114.04 3553.35,1114.04 3415.85,1256.96 3443.35,1256.96 3470.85,1256.96 3498.35,1256.96 3525.85,1256.96 3553.35,1256.96 3415.85,1282.88 3443.35,1282.88 3470.85,1282.88 3498.35,1282.88 3525.85,1282.88 3553.35,1282.88 3415.85,1308.81 3443.35,1308.81 3470.85,1308.81 3498.35,1308.81 3525.85,1308.81 3553.35,1308.81 3415.85,1334.73 3443.35,1334.73 3470.85,1334.73 3498.35,1334.73 3525.85,1334.73 3553.35,1334.73 3415.85,1360.66 3443.35,1360.66 3470.85,1360.66 3498.35,1360.66 3525.85,1360.66 3553.35,1360.66 3415.85,1386.59 3443.35,1386.59 3470.85,1386.59 3498.35,1386.59 3525.85,1386.59 3553.35,1386.59 3415.85,1412.51 3443.35,1412.51 3470.85,1412.51 3498.35,1412.51 3525.85,1412.51 3553.35,1412.51 3415.85,1438.44 3443.35,1438.44 3470.85,1438.44 3498.35,1438.44 3525.85,1438.44 3553.35,1438.44 3415.85,1464.37 3443.35,1464.37 3470.85,1464.37 3498.35,1464.37 3525.85,1464.37 3553.35,1464.37 3416.63,1535.05 3444.13,1535.05 3471.63,1535.05 3499.13,1535.05 3526.63,1535.05 3554.13,1535.05 3416.63,1560.98 3444.13,1560.98 3471.63,1560.98 3499.13,1560.98 3526.63,1560.98 3554.13,1560.98 3416.63,1586.9 3444.13,1586.9 3471.63,1586.9 3499.13,1586.9 3526.63,1586.9 3554.13,1586.9 3416.63,1612.83 3444.13,1612.83 3471.63,1612.83 3499.13,1612.83 3526.63,1612.83 3554.13,1612.83 3416.63,1638.76 3444.13,1638.76 3471.63,1638.76 3499.13,1638.76 3526.63,1638.76 3554.13,1638.76 3416.63,1664.68 3444.13,1664.68 3471.63,1664.68 3499.13,1664.68 3526.63,1664.68 3554.13,1664.68 3416.63,1690.61 3444.13,1690.61 3471.63,1690.61 3499.13,1690.61 3526.63,1690.61 3554.13,1690.61 3416.22,1879.28 3443.72,1879.28 3471.22,1879.28 3498.72,1879.28 3526.22,1879.28 3553.72,1879.28 3416.22,1905.2 3443.72,1905.2 3471.22,1905.2 3498.72,1905.2 3526.22,1905.2 3553.72,1905.2 5202.52,1928.63 5250.27,1928.58 5302.62,1928.58 5354.97,1928.58 5407.32,1928.58 5459.67,1928.58 5512.02,1928.58 5564.37,1928.58 5616.72,1928.58 5669.07,1928.58 5721.42,1928.58 5773.77,1928.58 5826.12,1928.58 5878.47,1928.58 5930.82,1928.58 5983.17,1928.58 6035.52,1928.58 3416.22,1931.13 3443.72,1931.13 3471.22,1931.13 3498.72,1931.13 3526.22,1931.13 3553.72,1931.13 5178.71,1945.99 3416.22,1957.05 3443.72,1957.05 3471.22,1957.05 3498.72,1957.05 3526.22,1957.05 3553.72,1957.05 5250,1972.74 5302.35,1972.74 5354.7,1972.74 5407.05,1972.74 5459.4,1972.74 5511.75,1972.74 5564.1,1972.74 5616.45,1972.74 5668.8,1972.74 5721.15,1972.74 5773.5,1972.74 5825.85,1972.74 5878.2,1972.74 5930.55,1972.74 5982.9,1972.74 6035.25,1972.74 3416.22,1982.98 3443.72,1982.98 3471.22,1982.98 3498.72,1982.98 3526.22,1982.98 3553.72,1982.98 5230.32,1991.46 5178.24,1994.78 3416.22,2008.91 3443.72,2008.91 3471.22,2008.91 3498.72,2008.91 3526.22,2008.91 3553.72,2008.91 3416.22,2034.83 3443.72,2034.83 3471.22,2034.83 3498.72,2034.83 3526.22,2034.83 3553.72,2034.83 5230.32,2038.95 5178.24,2042.27 5230.32,2086.43 5178.24,2089.75 3415.85,2106.63 3443.35,2106.63 3470.85,2106.63 3498.35,2106.63 3525.85,2106.63 3553.35,2106.63 3415.85,2132.56 3443.35,2132.56 3470.85,2132.56 3498.35,2132.56 3525.85,2132.56 3553.35,2132.56 5230.32,2133.92 5178.24,2137.24 3415.85,2158.48 3443.35,2158.48 3470.85,2158.48 3498.35,2158.48 3525.85,2158.48 3553.35,2158.48 5230.32,2181.4 3415.85,2184.41 3443.35,2184.41 3470.85,2184.41 3498.35,2184.41 3525.85,2184.41 3553.35,2184.41 5178.24,2184.72 3415.85,2210.34 3443.35,2210.34 3470.85,2210.34 3498.35,2210.34 3525.85,2210.34 3553.35,2210.34 5230.32,2228.89 5178.24,2232.21 3415.85,2236.26 3443.35,2236.26 3470.85,2236.26 3498.35,2236.26 3525.85,2236.26 3553.35,2236.26 3415.85,2262.19 3443.35,2262.19 3470.85,2262.19 3498.35,2262.19 3525.85,2262.19 3553.35,2262.19 5178.24,2276.37 5230.32,2276.37 3415.85,2288.12 3443.35,2288.12 3470.85,2288.12 3498.35,2288.12 3525.85,2288.12 3553.35,2288.12 3415.85,2314.04 3443.35,2314.04 3470.85,2314.04 3498.35,2314.04 3525.85,2314.04 3553.35,2314.04 5178.24,2320.53 5230.32,2323.85 5178.24,2368.02 5230.32,2371.34 5178.24,2415.5 5230.32,2418.82 3415.85,2456.95 3443.35,2456.95 3470.85,2456.95 3498.35,2456.95 3525.85,2456.95 3553.35,2456.95 5178.24,2462.99 5230.32,2466.31 3415.85,2482.88 3443.35,2482.88 3470.85,2482.88 3498.35,2482.88 3525.85,2482.88 3553.35,2482.88 3415.85,2508.81 3443.35,2508.81 3470.85,2508.81 3498.35,2508.81 3525.85,2508.81 3553.35,2508.81 5178.24,2510.47 5230.32,2513.79 3415.85,2534.73 3443.35,2534.73 3470.85,2534.73 3498.35,2534.73 3525.85,2534.73 3553.35,2534.73 5178.24,2557.96 3415.85,2560.66 3443.35,2560.66 3470.85,2560.66 3498.35,2560.66 3525.85,2560.66 3553.35,2560.66 5230.32,2561.28 5250,2580 5302.35,2580 5354.7,2580 5407.05,2580 5459.4,2580 5511.75,2580 5564.1,2580 5616.45,2580 5668.8,2580 5721.15,2580 5773.5,2580 5825.85,2580 5878.2,2580 5930.55,2580 5982.9,2580 6035.25,2580 3415.85,2586.59 3443.35,2586.59 3470.85,2586.59 3498.35,2586.59 3525.85,2586.59 3553.35,2586.59 5178.24,2605.44 3415.85,2612.51 3443.35,2612.51 3470.85,2612.51 3498.35,2612.51 3525.85,2612.51 3553.35,2612.51 5197.92,2624.16 5250.27,2624.16 5302.62,2624.16 5354.97,2624.16 5407.32,2624.16 5459.67,2624.16 5512.02,2624.16 5564.37,2624.16 5616.72,2624.16 5669.07,2624.16 5721.42,2624.16 5773.77,2624.16 5826.12,2624.16 5878.47,2624.16 5930.82,2624.16 5983.17,2624.16 6035.52,2624.16 3415.85,2638.44 3443.35,2638.44 3470.85,2638.44 3498.35,2638.44 3525.85,2638.44 3553.35,2638.44 3415.85,2664.36 3443.35,2664.36 3470.85,2664.36 3498.35,2664.36 3525.85,2664.36 3553.35,2664.36 3416.02,2715.91 3443.52,2715.91 3471.02,2715.91 3498.52,2715.91 3526.02,2715.91 3553.52,2715.91 3416.02,2741.84 3443.52,2741.84 3471.02,2741.84 3498.52,2741.84 3526.02,2741.84 3553.52,2741.84 3416.02,2767.76 3443.52,2767.76 3471.02,2767.76 3498.52,2767.76 3526.02,2767.76 3553.52,2767.76 3416.02,2793.69 3443.52,2793.69 3471.02,2793.69 3498.52,2793.69 3526.02,2793.69 3553.52,2793.69 3416.02,2819.61 3443.52,2819.61 3471.02,2819.61 3498.52,2819.61 3526.02,2819.61 3553.52,2819.61 3416.02,2845.54 3443.52,2845.54 3471.02,2845.54 3498.52,2845.54 3526.02,2845.54 3553.52,2845.54 3416.02,2871.47 3443.52,2871.47 3471.02,2871.47 3498.52,2871.47 3526.02,2871.47 3553.52,2871.47
  other v2: 5308.73,2050 5348.73,2050 5388.73,2050 5875,2050 5915,2050 5955,2050 5995,2050 5308.73,2090 5875,2090 5915,2090 5955,2090 5995,2090 5308.73,2130 5875,2130 5915,2130 5955,2130 5995,2130 5875,2170 5915,2170 5955,2170 5995,2170 5875,2210 5915,2210 5955,2210 5995,2210 5875,2250 5915,2250 5955,2250 5995,2250 5875,2300 5915,2300 5955,2300 5995,2300 5875,2340 5915,2340 5955,2340 5995,2340 5875,2380 5915,2380 5955,2380 5995,2380 5308.73,2420 5875,2420 5915,2420 5955,2420 5995,2420 5308.73,2460 5875,2460 5915,2460 5955,2460 5995,2460 5308.73,2500 5348.73,2500 5388.73,2500 5875,2500 5915,2500 5955,2500 5995,2500
VOUT_7: C15.1 JP6.1 R20.2 U1.7 | length 3010.8
  Top Layer w10: 2608.21,1666.32 U1.7@2608.21,1680.51
  Top Layer w13: 2607.89,1665.41 2660.67,1612.64
  Top Layer w14: 2607.89,1665.41 U1.7@2607.89,1686.41
  Top Layer w20: v1@2647.2,1594.18 2663.05,1610.02 C15.1@2663.01,1578.75 ; R20.2@3715.08,1774.24 3715.08,1781.45 3820.36,1781.45 JP6.1@3826.55,1787.64
  Signal Layer 2 w20: v1(2647.2,1593.1) 2647.97,1592.33 2656.34,1592.33 2676.65,1572.02 2676.65,847.84 2702.98,821.51 2942.19,821.51 2990.9,870.22 2990.9,1553.88 3061.77,1624.74 3173.23,1624.74 3256.62,1708.13 3256.62,1726.93 3302.39,1772.7 3821.31,1772.7 JP6.1@3823.16,1774.54
pads on no net: FID1.1 FID2.1 FID3.1 H1.1 H2.1 H3.1 H4.1 H5.0 H6.0 H7.0 H8.0 J9.3 J10.3 J13.1 J13.2 J13.3 J13.4 J13.5 J13.7 J13.8 SH-JP1.0 SH-JP2.0 SH-JP3.0 SH-JP4.0 SH-JP5.0 SH-JP6.0

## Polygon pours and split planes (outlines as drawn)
GND on Top Layer "TOP_LAYER_GND_P003" (solid, pour order 3): 3657.15,1079.52 3663.46,1085.83 3850.51,1085.83 3856.76,1079.59 3856.76,966.52 3822.57,932.33 3664.89,932.33 3657.15,940.07
GND on Top Layer "TOP_LAYER_GND_P005" (solid, pour order 5): 3657.15,2498.37 3663.46,2492.06 3850.51,2492.06 3856.76,2498.3 3856.76,2616.46 3827.65,2645.56 3664.89,2645.56 3657.15,2637.82
GND on Top Layer "TOP_LAYER_GND_P008" (solid, pour order 8): 3657.15,2138.03 3663.98,2131.2 3849.99,2131.2 3856.76,2137.97 3856.76,2248.84 3820.36,2285.23 3664.89,2285.23 3657.15,2277.49
NetQ5_4 on Top Layer "TOP_LAYER_NETQ5_4_P009" (solid, pour order 9): 3365.82,925.59 3365.85,950.75 3248.25,950.75 3248.25,903.8 3251.31,900.75 3282.34,900.75 3340.98,900.75
NetQ6_4 on Top Layer "TOP_LAYER_NETQ6_4_P015" (solid, pour order 15): 3009.87,866.09 3009.97,950.41 2892.37,950.41 2892.37,915.7 2909.85,898.21 2932.26,898.21 2945.22,885.25 2945.22,854.78 2946.36,853.64 2997.42,853.64
NetQ3_4 on Top Layer "TOP_LAYER_NETQ3_4_P016" (solid, pour order 16): 3366.87,2066.09 3366.97,2150.41 3249.37,2150.41 3249.37,2115.7 3263.64,2101.43 3286.05,2101.43 3299.2,2088.28 3299.2,2057.05 3302.61,2053.64 3354.42,2053.64
GND on Top Layer "TOP_LAYER_GND_P055" (solid, pour order 55): 3693.46,1536.21 3683.96,1526.71 3665.01,1526.71 3656.91,1534.81 3656.91,1623.47 3663.1,1629.67 3682.79,1629.67 3693.46,1618.99
GND on Top Layer "TOP_LAYER_GND_P057" (solid, pour order 57): 3693.46,2033.06 3683.96,2042.56 3665.01,2042.56 3656.91,2034.45 3656.91,1945.79 3663.1,1939.6 3682.79,1939.6 3693.46,1950.27
GND on Top Layer "TOP_LAYER_GND_P067" (solid, pour order 67): 3692.85,853.4 3683.35,862.9 3664.4,862.9 3656.3,854.79 3656.3,766.13 3662.49,759.94 3682.18,759.94 3692.85,770.61
GND on Top Layer "TOP_LAYER_GND_P073" (solid, pour order 73): 3692.85,2714.06 3683.35,2704.57 3664.4,2704.57 3656.3,2712.67 3656.3,2801.33 3662.49,2807.52 3682.18,2807.52 3692.85,2796.85
NetQ1_4 on Top Layer "TOP_LAYER_NETQ1_4_P075" (solid, pour order 75): 3367.36,1219.87 3367.46,1300.42 3249.86,1300.42 3249.86,1265.7 3259.06,1256.5 3277.86,1256.5 3296.87,1237.48 3296.87,1209.22 3300.46,1205.63 3353.12,1205.63
NetQ7_4 on Top Layer "TOP_LAYER_NETQ7_4_P076" (solid, pour order 76): 3367.36,2420.87 3367.46,2501.42 3249.86,2501.42 3249.86,2466.7 3259.06,2457.5 3277.86,2457.5 3296.87,2438.48 3296.87,2410.22 3300.46,2406.63 3353.12,2406.63
GND on Top Layer "TOP_LAYER_GND_P077" (solid, pour order 77): 4837.81,1568.96 4811.84,1542.99 4728.91,1542.99 4701.68,1570.23 4701.68,1728.87 4835.84,1728.87 4837.81,1726.91
GND on Top Layer "TOP_LAYER_GND_P078" (solid, pour order 78): 4387.81,1568.96 4361.84,1542.99 4278.91,1542.99 4251.68,1570.23 4251.68,1728.87 4385.84,1728.87 4387.81,1726.91
GND on Top Layer "TOP_LAYER_GND_P079" (solid, pour order 79): 4701.86,1951.65 4727.83,1977.62 4810.76,1977.62 4837.99,1950.39 4837.99,1791.75 4703.82,1791.75 4701.86,1793.71
GND on Top Layer "TOP_LAYER_GND_P080" (solid, pour order 80): 4252.19,1961.04 4278.16,1987.01 4361.09,1987.01 4388.32,1959.77 4388.32,1801.13 4254.16,1801.13 4252.19,1803.09
GND on Top Layer "TOP_LAYER_GND_P084" (solid, pour order 84): 3657.15,1432.2 3664.39,1439.44 3848.13,1439.44 3856.76,1430.81 3856.76,1313.4 3828.36,1285 3664.89,1285 3657.15,1292.74
AGND on Top Layer "TOP_LAYER_AGND_P085" (solid, remove dead copper, pour order 85): 25.49,4074.51 25.49,2648.47 906.75,2648.47 1107.26,2848.98 1622.57,2848.98 1805.16,3031.57 1805.16,3320.09 2011.42,3526.35 5445.53,3526.35 5541.34,3430.54 5541.34,2950.62 5588.41,2903.54 6072.83,2903.54 6072.83,4074.51
L2 on Top Layer "TOP_LAYER_L2_P088" (solid, remove dead copper, pour order 88): 2193,2960.88 2218.34,2935.54 2456.68,2935.73 2456.68,2838.87 2656.36,2838.87 2815.5,2993.63 2815.5,3125.83 2614.78,3326.55 2358.59,3326.55 2193,3160.95
L1 on Top Layer "TOP_LAYER_L1_P089" (solid, remove dead copper, pour order 89): 2194,569.12 2220.52,595.64 2461.63,595.86 2462.2,693.36 2624.2,693.36 2822.58,538.35 2822.58,407.08 2621.85,206.35 2356.7,206.35 2194,369.05
NetQ2_4 on Top Layer "TOP_LAYER_NETQ2_4_P093" (solid, pour order 93): 3009.87,1216.09 3009.97,1300.41 2892.37,1300.41 2892.37,1265.7 2909.85,1248.21 2932.26,1248.21 2945.22,1235.25 2945.22,1204.78 2946.36,1203.64 2997.42,1203.64
NetQ8_4 on Top Layer "TOP_LAYER_NETQ8_4_P094" (solid, pour order 94): 3009.87,2417.09 3009.97,2501.41 2892.37,2501.41 2892.37,2466.7 2909.85,2449.21 2932.26,2449.21 2945.22,2436.25 2945.22,2405.78 2946.36,2404.64 2997.42,2404.64
RS1 on Top Layer "Top Layer-RS^1" (solid, pour order 99): 1892.22,806.95 2232.46,806.95 2232.46,838.61 2439.25,838.61 2439.25,622.23 2142.23,622.23 2062.62,542.62 1991,542.62 1892.28,641.33
RS2 on Top Layer "Top Layer-RS2" (solid, pour order 100): 1893.88,2725 2230.01,2725 2230.01,2694.27 2440.24,2694.27 2440.24,2889.98 2418.51,2911.7 2141.92,2911.7 2063.61,2990 1991.99,2990 1894.07,2892.08
NetC10_2 on Top Layer "TOP_LAYER_NETC10_2_P101" (solid, pour order 101): 2907.04,2386.68 2956.54,2386.68 2972.85,2370.37 2992.67,2370.37 2992.67,2335.37 2992.8,2335.24 2972.77,2335.24 2955.4,2317.87 2907.04,2317.87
